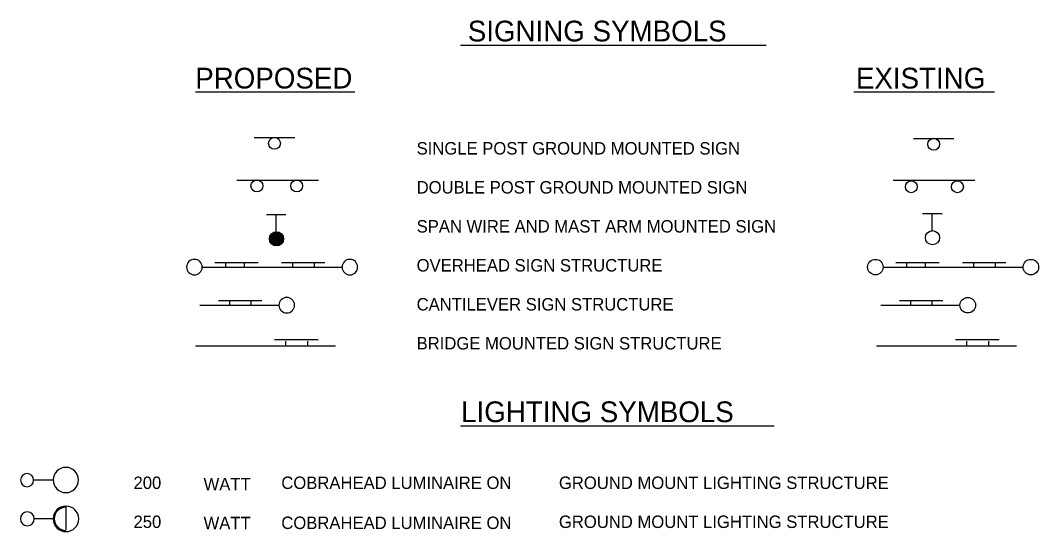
# Model space of a CAD drawing. Extents: x 10019.5 to 10026.1, y 9984.8 to 9994.8.
# Drawn here: x 10019.513 to 10024.425, y 9992.329 to 9994.794 of the extents above; entities that cross this region are included whole.
import ezdxf

# ---------------------------------------------------------------- set-up
doc = ezdxf.new("R2010")
doc.units = 0
for name, color, linetype in [('DETL-LINE', 7, 'Continuous'), ('DETL-NOTE', 7, 'Continuous'), ('DETL-TITL', 7, 'Continuous')]:
    doc.layers.add(name, color=color, linetype=linetype)

# ---------------------------------------------------------------- blocks, each defined once
blk = doc.blocks.new('34')
at = {"layer": 'DETL-LINE'}
for p, q in [((26.2, 9.5), (26.2, -11.2)), ((7.1, -0.7), (26.2, -0.7))]:
    blk.add_line(p, q, dxfattribs=at)
blk.add_circle((0.6, -1.2), 7.5, dxfattribs=at)
blk = doc.blocks.new('63')
at = {"layer": 'DETL-LINE'}
for p, q in [((-25.1, -10.2), (-25.1, 10.4)), ((-7, 1), (8, 1)), ((-7, 0), (8, 0)), ((-6.8, 2), (7.8, 2)), ((-6.5, 3), (7.5, 3)), ((-6.1, 4), (7.1, 4)), ((-5.4, 5), (6.4, 5)), ((-4.5, 6), (5.5, 6)), ((-3, 7), (4.1, 7)), ((-6, 0), (-25.1, 0)), ((-6.9, -1), (7.9, -1)), ((-6.6, -2), (7.6, -2)), ((-6.2, -3), (7.2, -3)), ((-5.6, -4), (6.6, -4)), ((-4.7, -5), (5.7, -5)), ((-3.4, -6), (4.4, -6)), ((-0.8, -7), (1.8, -7))]:
    blk.add_line(p, q, dxfattribs=at)
blk.add_circle((0.5, 0.4), 7.5, dxfattribs=at)

msp = doc.modelspace()

# ---------------------------------------------------------------- linework, layer by layer
at = {"layer": 'DETL-LINE'}
for p, q in [((10020.6417, 9994.2294), (10020.8367, 9994.2294)), ((10023.8217, 9994.2254), (10024.0167, 9994.2254)), ((10020.5567, 9994.0244), (10020.9517, 9994.0244)), ((10023.7227, 9994.0244), (10024.1177, 9994.0244)), ((10020.4505, 9993.6265), (10020.6605, 9993.6265)), ((10020.5025, 9993.6265), (10020.5025, 9993.6045)), ((10020.5925, 9993.6265), (10020.5925, 9993.6045)), ((10020.7725, 9993.6265), (10020.9825, 9993.6265)), ((10020.8255, 9993.6265), (10020.8255, 9993.6045)), ((10020.9305, 9993.6265), (10020.9305, 9993.6045)), ((10023.7355, 9993.6265), (10023.9455, 9993.6265)), ((10023.7875, 9993.6265), (10023.7875, 9993.6045)), ((10023.8775, 9993.6265), (10023.8775, 9993.6045)), ((10024.0575, 9993.6265), (10024.2675, 9993.6265)), ((10024.1105, 9993.6265), (10024.1105, 9993.6045)), ((10024.2155, 9993.6265), (10024.2155, 9993.6045)), ((10020.3905, 9993.6045), (10021.0651, 9993.6045)), ((10023.6755, 9993.6045), (10024.3505, 9993.6045)), ((10020.3786, 9993.4211), (10020.7607, 9993.4211)), ((10020.4686, 9993.4431), (10020.6786, 9993.4431)), ((10020.5216, 9993.4431), (10020.5216, 9993.4211)), ((10020.6256, 9993.4431), (10020.6256, 9993.4211)), ((10023.6635, 9993.4211), (10024.0465, 9993.4211)), ((10023.7535, 9993.4431), (10023.9635, 9993.4431)), ((10023.8065, 9993.4431), (10023.8065, 9993.4211)), ((10023.9105, 9993.4431), (10023.9105, 9993.4211)), ((10020.3577, 9993.225), (10021.0327, 9993.225)), ((10020.7397, 9993.255), (10020.9497, 9993.255)), ((10020.7927, 9993.248), (10020.7927, 9993.225)), ((10020.8977, 9993.248), (10020.8977, 9993.225)), ((10023.6427, 9993.225), (10024.3177, 9993.225)), ((10024.0247, 9993.255), (10024.2347, 9993.255)), ((10024.0777, 9993.248), (10024.0777, 9993.225)), ((10024.1827, 9993.248), (10024.1827, 9993.225)), ((10019.672, 9992.5777), (10019.575, 9992.5777)), ((10019.732, 9992.4507), (10019.732, 9992.4437)), ((10019.732, 9992.4437), (10019.732, 9992.3377)), ((10019.672, 9992.3907), (10019.582, 9992.3907))]:
    msp.add_line(p, q, dxfattribs=at)
for centre, radius in [((10020.7391, 9994.2013), 0.0286), ((10023.9189, 9994.1971), 0.0286), ((10020.6541, 9993.9961), 0.0286), ((10020.8463, 9993.9961), 0.0286), ((10023.8108, 9993.9919), 0.0286), ((10024.0333, 9993.9919), 0.0286), ((10023.6376, 9993.6046), 0.0375), ((10024.3876, 9993.6046), 0.0375), ((10024.0831, 9993.4211), 0.0375)]:
    msp.add_circle(centre, radius, dxfattribs=at)
for centre, radius, start, end in [((10020.3526, 9993.6046), 0.0375, 0, 180), ((10021.1026, 9993.6046), 0.0375, 0, 180), ((10020.3526, 9993.6046), 0.0375, 180, 0), ((10021.1026, 9993.6046), 0.0375, 180, 0), ((10020.7982, 9993.4211), 0.0375, 0, 180), ((10020.7982, 9993.4211), 0.0375, 180, 0), ((10019.7323, 9992.5782), 0.0608, 0, 180), ((10019.5456, 9992.5773), 0.0315, 0, 180), ((10019.5456, 9992.5773), 0.0315, 180, 0), ((10019.7323, 9992.5782), 0.0608, 180, 0), ((10019.7329, 9992.3907), 0.0615, 90, 270), ((10019.7327, 9992.3911), 0.0559, 90, 270), ((10019.7329, 9992.3907), 0.0615, 270, 90), ((10019.5467, 9992.3907), 0.0335, 90, 270), ((10019.5467, 9992.3907), 0.0335, 90, 270), ((10019.5467, 9992.3907), 0.0335, 270, 90), ((10019.5467, 9992.3907), 0.0335, 270, 90)]:
    msp.add_arc(centre, radius, start, end, dxfattribs=at)
at = {"layer": 'DETL-TITL'}
for p, q in [((10021.6362, 9994.6753), (10023.1106, 9994.6753)), ((10020.3577, 9994.4494), (10021.1264, 9994.4494)), ((10023.5343, 9994.4494), (10024.212, 9994.4494)), ((10021.6362, 9992.8395), (10023.1501, 9992.8395))]:
    msp.add_line(p, q, dxfattribs=at)

# ---------------------------------------------------------------- block references
at = {"layer": 'DETL-LINE', "xscale": 0.0045833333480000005, "yscale": 0.0045833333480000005}
for name, p, rotation in [('63', (10020.7467, 9993.7434), -90.00000000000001), ('34', (10023.9077, 9993.7434), 90)]:
    msp.add_blockref(name, p, dxfattribs=dict(at, rotation=rotation))

# ---------------------------------------------------------------- texts
at = {"layer": 'DETL-NOTE'}
for s, p in [('SINGLE POST GROUND MOUNTED SIGN', (10021.4247, 9994.1474)), ('DOUBLE POST GROUND MOUNTED SIGN', (10021.4247, 9993.9594)), ('SPAN WIRE AND MAST ARM MOUNTED SIGN', (10021.4247, 9993.7714)), ('OVERHEAD SIGN STRUCTURE', (10021.4247, 9993.5834)), ('CANTILEVER SIGN STRUCTURE', (10021.4247, 9993.3954)), ('BRIDGE MOUNTED SIGN STRUCTURE', (10021.4247, 9993.2074)), ('200', (10020.059, 9992.5347)), ('WATT', (10020.397, 9992.5277)), ('COBRAHEAD LUMINAIRE ON', (10020.772, 9992.5347)), ('GROUND MOUNT LIGHTING STRUCTURE', (10022.111, 9992.5347)), ('250', (10020.059, 9992.3467)), ('WATT', (10020.397, 9992.3407)), ('COBRAHEAD LUMINAIRE ON', (10020.772, 9992.3417)), ('GROUND MOUNT LIGHTING STRUCTURE', (10022.111, 9992.3467))]:
    msp.add_text(s, height=0.06, dxfattribs=at).set_placement(p)
at = {"layer": 'DETL-TITL'}
for s, height, p in [('SIGNING SYMBOLS', 0.100002, (10021.6715, 9994.6928)), ('PROPOSED', 0.1, (10020.3567, 9994.4658)), ('EXISTING', 0.1, (10023.5437, 9994.4658)), ('LIGHTING SYMBOLS', 0.100002, (10021.6393, 9992.857))]:
    msp.add_text(s, height=height, dxfattribs=at).set_placement(p)

doc.saveas('drawing.dxf')
